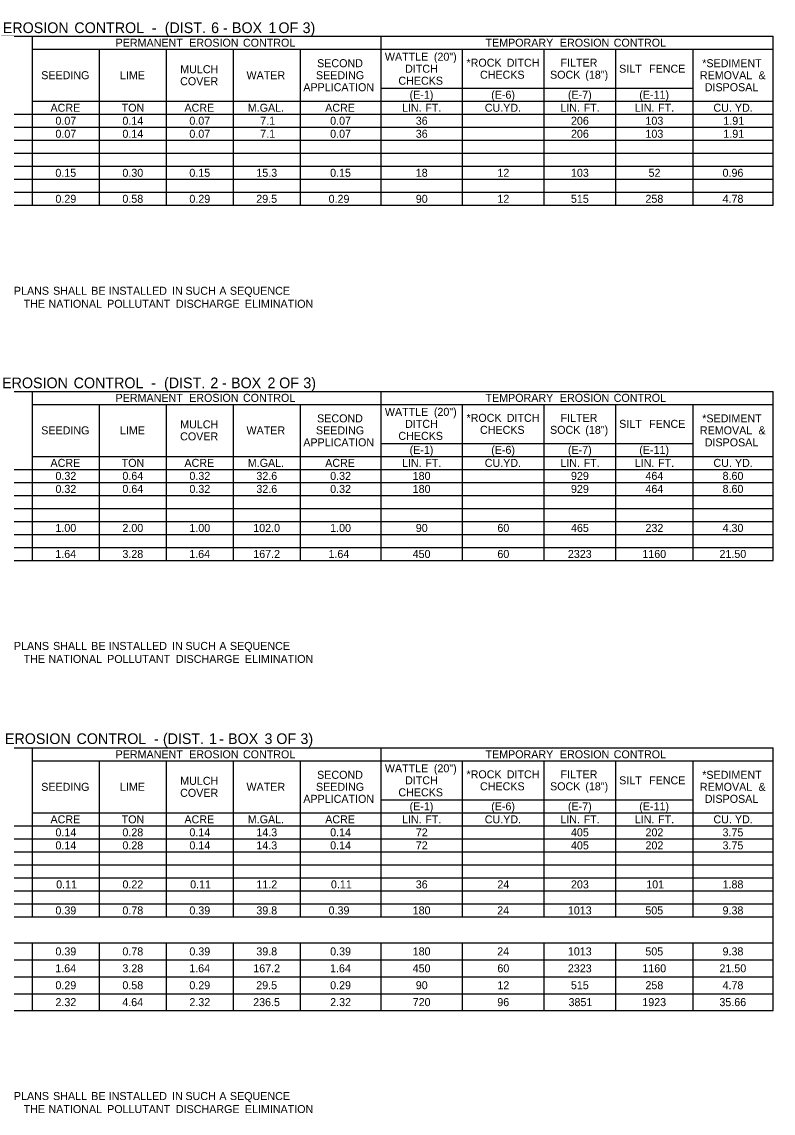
# Model space of a CAD drawing. Extents: x 542596 to 1930787, y -1948294 to 596640.
# Drawn here: x 561680 to 562244, y -1946944 to -1946126 of the extents above; entities that cross this region are included whole.
import ezdxf

# ---------------------------------------------------------------- set-up
doc = ezdxf.new("R2010")
doc.units = 0
doc.layers.add('Default', color=7, linetype='Continuous')

msp = doc.modelspace()

# ---------------------------------------------------------------- linework, layer by layer
at = {"layer": 'Default'}
for p, q in [((561328.63, -1946137.12), (562243.67, -1946137.12)), ((561688.41, -1946263.87), (561688.41, -1946137.12)), ((561949.71, -1946146.87), (561949.71, -1946137.12)), ((561949.71, -1946263.87), (561949.71, -1946137.12)), ((562243.67, -1946195.62), (562243.67, -1946137.12)), ((561688.41, -1946146.87), (562243.67, -1946146.87)), ((561738.62, -1946263.87), (561738.62, -1946146.87)), ((561788.83, -1946263.87), (561788.83, -1946146.87)), ((561839.04, -1946263.87), (561839.04, -1946146.87)), ((561889.26, -1946263.87), (561889.26, -1946146.87)), ((562010.64, -1946263.87), (562010.64, -1946146.87)), ((562072.07, -1946263.87), (562072.07, -1946146.87)), ((562125.69, -1946263.87), (562125.69, -1946146.87)), ((562183.71, -1946263.87), (562183.71, -1946146.87)), ((561949.71, -1946176.12), (562183.71, -1946176.12)), ((561688.41, -1946185.87), (562183.71, -1946185.87)), ((561738.62, -1946263.87), (561738.62, -1946185.87)), ((561788.83, -1946254.12), (561788.83, -1946185.87)), ((561839.04, -1946254.12), (561839.04, -1946185.87)), ((561889.26, -1946254.12), (561889.26, -1946185.87)), ((561949.71, -1946254.12), (561949.71, -1946185.87)), ((562010.64, -1946254.12), (562010.64, -1946185.87)), ((562072.07, -1946254.12), (562072.07, -1946185.87)), ((562125.69, -1946263.87), (562125.69, -1946185.87)), ((562183.71, -1946185.87), (562243.67, -1946185.87)), ((562183.71, -1946263.87), (562183.71, -1946185.87)), ((561328.63, -1946195.62), (562243.67, -1946195.62)), ((562243.67, -1946254.12), (562243.67, -1946195.62)), ((561328.63, -1946205.37), (562243.67, -1946205.37)), ((561328.63, -1946215.12), (562243.67, -1946215.12)), ((561328.63, -1946224.87), (562243.67, -1946224.87)), ((561328.63, -1946234.62), (562243.67, -1946234.62)), ((561328.63, -1946244.37), (562243.67, -1946244.37)), ((561328.63, -1946254.12), (562243.67, -1946254.12)), ((561688.41, -1946263.87), (561688.41, -1946254.12)), ((562183.71, -1946254.12), (562243.67, -1946254.12)), ((562243.67, -1946263.87), (562243.67, -1946254.12)), ((561328.63, -1946263.87), (562243.67, -1946263.87)), ((561328.63, -1946403.3), (562243.67, -1946403.3)), ((561688.41, -1946530.05), (561688.41, -1946403.3)), ((561949.71, -1946413.05), (561949.71, -1946403.3)), ((561949.71, -1946530.05), (561949.71, -1946403.3)), ((562243.67, -1946461.8), (562243.67, -1946403.3)), ((561688.41, -1946413.05), (562243.67, -1946413.05)), ((561738.62, -1946530.05), (561738.62, -1946413.05)), ((561788.83, -1946530.05), (561788.83, -1946413.05)), ((561839.04, -1946530.05), (561839.04, -1946413.05)), ((561889.26, -1946530.05), (561889.26, -1946413.05)), ((562010.64, -1946530.05), (562010.64, -1946413.05)), ((562072.07, -1946530.05), (562072.07, -1946413.05)), ((562125.69, -1946530.05), (562125.69, -1946413.05)), ((562183.71, -1946530.05), (562183.71, -1946413.05)), ((561949.71, -1946442.3), (562183.71, -1946442.3)), ((561688.41, -1946452.05), (562183.71, -1946452.05)), ((561738.62, -1946530.05), (561738.62, -1946452.05)), ((561788.83, -1946520.3), (561788.83, -1946452.05)), ((561839.04, -1946520.3), (561839.04, -1946452.05)), ((561889.26, -1946520.3), (561889.26, -1946452.05)), ((561949.71, -1946520.3), (561949.71, -1946452.05)), ((562010.64, -1946520.3), (562010.64, -1946452.05)), ((562072.07, -1946520.3), (562072.07, -1946452.05)), ((562125.69, -1946530.05), (562125.69, -1946452.05)), ((562183.71, -1946452.05), (562243.67, -1946452.05)), ((562183.71, -1946530.05), (562183.71, -1946452.05)), ((561328.63, -1946461.8), (562243.67, -1946461.8)), ((562243.67, -1946520.3), (562243.67, -1946461.8)), ((561328.63, -1946471.55), (562243.67, -1946471.55)), ((561328.63, -1946481.3), (562243.67, -1946481.3)), ((561328.63, -1946491.05), (562243.67, -1946491.05)), ((561328.63, -1946500.8), (562243.67, -1946500.8)), ((561328.63, -1946510.55), (562243.67, -1946510.55)), ((561328.63, -1946520.3), (562243.67, -1946520.3)), ((561688.41, -1946530.05), (561688.41, -1946520.3)), ((562183.71, -1946520.3), (562243.67, -1946520.3)), ((562243.67, -1946530.05), (562243.67, -1946520.3)), ((561328.63, -1946530.05), (562243.67, -1946530.05)), ((561328.63, -1946670.45), (562243.67, -1946670.45)), ((561688.41, -1946797.2), (561688.41, -1946670.45)), ((561949.71, -1946680.2), (561949.71, -1946670.45)), ((561949.71, -1946797.2), (561949.71, -1946670.45)), ((562243.67, -1946728.95), (562243.67, -1946670.45)), ((561688.41, -1946680.2), (562243.67, -1946680.2)), ((561738.62, -1946797.2), (561738.62, -1946680.2)), ((561788.83, -1946797.2), (561788.83, -1946680.2)), ((561839.04, -1946797.2), (561839.04, -1946680.2)), ((561889.26, -1946797.2), (561889.26, -1946680.2)), ((562010.64, -1946797.2), (562010.64, -1946680.2)), ((562072.07, -1946797.2), (562072.07, -1946680.2)), ((562125.69, -1946797.2), (562125.69, -1946680.2)), ((562183.71, -1946797.2), (562183.71, -1946680.2)), ((561949.71, -1946709.45), (562183.71, -1946709.45)), ((561688.41, -1946719.2), (562183.71, -1946719.2)), ((561738.62, -1946797.2), (561738.62, -1946719.2)), ((561788.83, -1946787.45), (561788.83, -1946719.2)), ((561839.04, -1946787.45), (561839.04, -1946719.2)), ((561889.26, -1946787.45), (561889.26, -1946719.2)), ((561949.71, -1946787.45), (561949.71, -1946719.2)), ((562010.64, -1946787.45), (562010.64, -1946719.2)), ((562072.07, -1946787.45), (562072.07, -1946719.2)), ((562125.69, -1946797.2), (562125.69, -1946719.2)), ((562183.71, -1946719.2), (562243.67, -1946719.2)), ((562183.71, -1946797.2), (562183.71, -1946719.2)), ((561328.63, -1946728.95), (562243.67, -1946728.95)), ((562243.67, -1946787.45), (562243.67, -1946728.95)), ((561328.63, -1946738.7), (562243.67, -1946738.7)), ((561328.63, -1946748.45), (562243.67, -1946748.45)), ((561328.63, -1946758.2), (562243.67, -1946758.2)), ((561328.63, -1946767.95), (562243.67, -1946767.95)), ((561328.63, -1946777.7), (562243.67, -1946777.7)), ((561328.63, -1946787.45), (562243.67, -1946787.45)), ((561688.41, -1946797.2), (561688.41, -1946787.45)), ((562183.71, -1946787.45), (562243.67, -1946787.45)), ((562243.67, -1946797.2), (562243.67, -1946787.45)), ((561328.63, -1946797.2), (562243.67, -1946797.2)), ((562243.67, -1946816.7), (562243.67, -1946797.2)), ((561328.63, -1946816.7), (562243.67, -1946816.7)), ((561328.63, -1946816.7), (562243.67, -1946816.7)), ((561688.41, -1946867.4), (561688.41, -1946816.7)), ((561738.62, -1946867.4), (561738.62, -1946816.7)), ((561788.83, -1946867.4), (561788.83, -1946816.7)), ((561839.04, -1946867.4), (561839.04, -1946816.7)), ((561889.26, -1946867.4), (561889.26, -1946816.7)), ((561949.71, -1946867.4), (561949.71, -1946816.7)), ((562010.64, -1946867.4), (562010.64, -1946816.7)), ((562072.07, -1946867.4), (562072.07, -1946816.7)), ((562125.69, -1946867.4), (562125.69, -1946816.7)), ((562183.71, -1946867.4), (562183.71, -1946816.7)), ((562243.67, -1946854.72), (562243.67, -1946816.7)), ((561328.63, -1946829.37), (562243.67, -1946829.37)), ((561738.62, -1946867.4), (561738.62, -1946829.37)), ((561788.83, -1946867.4), (561788.83, -1946829.37)), ((561839.04, -1946867.4), (561839.04, -1946829.37)), ((561889.26, -1946867.4), (561889.26, -1946829.37)), ((561949.71, -1946867.4), (561949.71, -1946829.37)), ((562010.64, -1946867.4), (562010.64, -1946829.37)), ((562072.07, -1946867.4), (562072.07, -1946829.37)), ((562125.69, -1946867.4), (562125.69, -1946829.37)), ((562183.71, -1946867.4), (562183.71, -1946829.37)), ((561328.63, -1946842.05), (562243.67, -1946842.05)), ((561328.63, -1946854.72), (562243.67, -1946854.72)), ((561688.41, -1946867.4), (561688.41, -1946854.72)), ((562243.67, -1946867.4), (562243.67, -1946854.72)), ((561328.63, -1946867.4), (562243.67, -1946867.4))]:
    msp.add_line(p, q, dxfattribs=at)

# ---------------------------------------------------------------- texts
for s, height, p in [('EROSION', 8, (561666.11, -1946134.79)), (' CONTROL', 8, (561716.77, -1946134.79)), (' -', 8, (561774.81, -1946134.79)), ('  (DIST.', 8, (561781.55, -1946134.79)), (' 6', 8, (561819.28, -1946134.79)), (' -', 8, (561828.2, -1946134.79)), (' BOX', 8, (561834.94, -1946134.79)), (' 1', 8, (561862.26, -1946134.79)), (' OF', 8, (561869.77, -1946134.79)), (' 3)', 8, (561887.88, -1946134.79)), ('PERMANENT', 6, (561750.67, -1946145)), (' EROSION', 6, (561803.6, -1946145)), (' CONTROL', 6, (561843.92, -1946145)), ('TEMPORARY', 6, (562027.97, -1946145)), (' EROSION', 6, (562081.55, -1946145)), (' CONTROL', 6, (562121.88, -1946145)), ('WATTLE', 6, (561952.54, -1946155.5)), (' (20")', 6, (561987.05, -1946155.5)), ('MULCH', 6, (561799.12, -1946164.87)), ('SECOND', 6, (561901.75, -1946160.37)), ('DITCH', 6, (561967.69, -1946164.5)), ('*ROCK', 6, (562013.74, -1946160)), (' DITCH', 6, (562041.67, -1946160)), ('FILTER', 6, (562084.23, -1946160)), ('SILT', 6, (562128.21, -1946164.5)), ('  FENCE', 6, (562146.2, -1946164.5)), ('*SEDIMENT', 6, (562190.48, -1946160.37)), ('SEEDING', 6, (561694.9, -1946169.37)), ('LIME', 6, (561753.92, -1946169.37)), ('WATER', 6, (561848.8, -1946169.37)), ('SEEDING', 6, (561900.87, -1946169.37)), ('CHECKS', 6, (562023.86, -1946169)), ('SOCK', 6, (562076.39, -1946169)), (' (18")', 6, (562100.6, -1946169)), ('REMOVAL', 6, (562188.73, -1946169.37)), (' &', 6, (562230.4, -1946169.37)), ('COVER', 6, (561799.05, -1946173.87)), ('APPLICATION', 6, (561891.4, -1946178.37)), ('CHECKS', 6, (561962.68, -1946173.5)), ('DISPOSAL', 6, (562192.38, -1946178.37)), ('(E-1)', 6, (561971.08, -1946184)), ('(E-6)', 6, (562032.26, -1946184)), ('(E-7)', 6, (562089.79, -1946184)), ('(E-11)', 6, (562143.28, -1946184)), ('ACRE', 6, (561701.84, -1946193.75)), ('TON', 6, (561755.21, -1946193.75)), ('ACRE', 6, (561802.27, -1946193.75)), ('M.GAL.', 6, (561849.77, -1946193.75)), ('ACRE', 6, (561907.81, -1946193.75)), ('LIN.', 6, (561965.38, -1946193.75)), (' FT.', 6, (561980.64, -1946193.75)), ('CU.YD.', 6, (562027.44, -1946193.75)), ('LIN.', 6, (562084.09, -1946193.75)), (' FT.', 6, (562099.35, -1946193.75)), ('LIN.', 6, (562139.91, -1946193.75)), (' FT.', 6, (562155.17, -1946193.75)), ('CU.', 6, (562198.89, -1946193.75)), (' YD.', 6, (562212.75, -1946193.75)), ('0.07', 6, (561705.55, -1946203.5)), ('0.14', 6, (561755.77, -1946203.5)), ('0.07', 6, (561805.97, -1946203.5)), ('7.1', 6, (561859.1, -1946203.5)), ('0.07', 6, (561911.52, -1946203.5)), ('36', 6, (561975.7, -1946203.5)), ('206', 6, (562092.08, -1946203.5)), ('103', 6, (562147.9, -1946203.5)), ('1.91', 6, (562206.3, -1946203.5)), ('0.07', 6, (561705.55, -1946213.25)), ('0.14', 6, (561755.77, -1946213.25)), ('0.07', 6, (561805.97, -1946213.25)), ('7.1', 6, (561859.1, -1946213.25)), ('0.07', 6, (561911.52, -1946213.25)), ('36', 6, (561975.7, -1946213.25)), ('206', 6, (562092.08, -1946213.25)), ('103', 6, (562147.9, -1946213.25)), ('1.91', 6, (562206.3, -1946213.25)), ('0.15', 6, (561705.52, -1946242.5)), ('0.30', 6, (561755.77, -1946242.5)), ('0.15', 6, (561805.95, -1946242.5)), ('15.3', 6, (561856.19, -1946242.5)), ('0.15', 6, (561911.49, -1946242.5)), ('18', 6, (561975.7, -1946242.5)), ('12', 6, (562036.92, -1946242.5)), ('103', 6, (562092.08, -1946242.5)), ('52', 6, (562150.26, -1946242.5)), ('0.96', 6, (562205.72, -1946242.5)), ('0.29', 6, (561705.55, -1946262)), ('0.58', 6, (561755.76, -1946262)), ('0.29', 6, (561805.98, -1946262)), ('29.5', 6, (561856.12, -1946262)), ('0.29', 6, (561910.36, -1946262)), ('90', 6, (561975.72, -1946262)), ('12', 6, (562036.91, -1946262)), ('515', 6, (562092.02, -1946262)), ('258', 6, (562147.9, -1946262)), ('4.78', 6, (562205.72, -1946262)), (' PLANS', 6, (561672.2, -1946330.92)), (' SHALL', 6, (561701.58, -1946330.92)), (' BE', 6, (561730.17, -1946330.92)), (' INSTALLED', 6, (561743.24, -1946330.92)), (' IN', 6, (561790.77, -1946330.92)), (' SUCH', 6, (561800.8, -1946330.92)), (' A', 6, (561826.21, -1946330.92)), (' SEQUENCE', 6, (561834.14, -1946330.92)), (' THE', 6, (561679.49, -1946340.67)), (' NATIONAL', 6, (561698.14, -1946340.67)), (' POLLUTANT', 6, (561742.1, -1946340.67)), (' DISCHARGE', 6, (561793.64, -1946340.67)), (' ELIMINATION', 6, (561845.36, -1946340.67)), ('EROSION', 8, (561665.57, -1946400.96)), (' CONTROL', 8, (561716.23, -1946400.96)), ('  (DIST.', 8, (561781.01, -1946400.96)), (' 2', 8, (561818.74, -1946400.96)), (' BOX', 8, (561834.24, -1946400.96)), (' 2', 8, (561861.55, -1946400.96)), (' OF', 8, (561870.31, -1946400.96)), (' 3)', 8, (561888.42, -1946400.96)), (' -', 8, (561774.27, -1946400.96)), (' -', 8, (561827.49, -1946400.96)), ('PERMANENT', 6, (561750.67, -1946411.17)), (' EROSION', 6, (561803.6, -1946411.17)), (' CONTROL', 6, (561843.92, -1946411.17)), ('TEMPORARY', 6, (562027.97, -1946411.17)), (' EROSION', 6, (562081.55, -1946411.17)), (' CONTROL', 6, (562121.88, -1946411.17)), ('SECOND', 6, (561901.75, -1946426.55)), ('WATTLE', 6, (561952.54, -1946421.67)), (' (20")', 6, (561987.05, -1946421.67)), ('*ROCK', 6, (562013.74, -1946426.17)), (' DITCH', 6, (562041.67, -1946426.17)), ('FILTER', 6, (562084.23, -1946426.17)), ('*SEDIMENT', 6, (562190.48, -1946426.55)), ('MULCH', 6, (561799.12, -1946431.05)), ('DITCH', 6, (561967.69, -1946430.67)), (' (18")', 6, (562100.6, -1946435.17)), ('SILT', 6, (562128.21, -1946430.67)), ('  FENCE', 6, (562146.2, -1946430.67)), ('SEEDING', 6, (561694.9, -1946435.55)), ('LIME', 6, (561753.92, -1946435.55)), ('COVER', 6, (561799.05, -1946440.05)), ('WATER', 6, (561848.8, -1946435.55)), ('SEEDING', 6, (561900.87, -1946435.55)), ('CHECKS', 6, (561962.68, -1946439.67)), ('CHECKS', 6, (562023.86, -1946435.17)), ('SOCK', 6, (562076.39, -1946435.17)), ('REMOVAL', 6, (562188.73, -1946435.55)), (' &', 6, (562230.4, -1946435.55)), ('APPLICATION', 6, (561891.4, -1946444.55)), ('(E-1)', 6, (561971.08, -1946450.17)), ('(E-6)', 6, (562032.26, -1946450.17)), ('(E-7)', 6, (562089.79, -1946450.17)), ('(E-11)', 6, (562143.28, -1946450.17)), ('DISPOSAL', 6, (562192.38, -1946444.55)), ('ACRE', 6, (561701.84, -1946459.92)), ('TON', 6, (561755.21, -1946459.92)), ('ACRE', 6, (561802.27, -1946459.92)), ('M.GAL.', 6, (561849.77, -1946459.92)), ('ACRE', 6, (561907.81, -1946459.92)), ('LIN.', 6, (561965.38, -1946459.92)), (' FT.', 6, (561980.64, -1946459.92)), ('CU.YD.', 6, (562027.44, -1946459.92)), ('LIN.', 6, (562084.09, -1946459.92)), (' FT.', 6, (562099.35, -1946459.92)), ('LIN.', 6, (562139.91, -1946459.92)), (' FT.', 6, (562155.17, -1946459.92)), ('CU.', 6, (562198.89, -1946459.92)), (' YD.', 6, (562212.75, -1946459.92)), ('0.32', 6, (561705.58, -1946469.67)), ('0.64', 6, (561755.77, -1946469.67)), ('0.32', 6, (561806, -1946469.67)), ('32.6', 6, (561856.19, -1946469.67)), ('0.32', 6, (561911.55, -1946469.67)), ('180', 6, (561973.39, -1946469.67)), ('929', 6, (562092.08, -1946469.67)), ('464', 6, (562147.91, -1946469.67)), ('8.60', 6, (562205.73, -1946469.67)), ('0.32', 6, (561705.58, -1946479.42)), ('0.64', 6, (561755.77, -1946479.42)), ('0.32', 6, (561806, -1946479.42)), ('32.6', 6, (561856.19, -1946479.42)), ('0.32', 6, (561911.55, -1946479.42)), ('180', 6, (561973.39, -1946479.42)), ('929', 6, (562092.08, -1946479.42)), ('464', 6, (562147.91, -1946479.42)), ('8.60', 6, (562205.73, -1946479.42)), ('1.00', 6, (561705.56, -1946508.67)), ('2.00', 6, (561755.77, -1946508.67)), ('1.00', 6, (561805.98, -1946508.67)), ('102.0', 6, (561853.87, -1946508.67)), ('1.00', 6, (561911.53, -1946508.67)), ('90', 6, (561975.72, -1946508.67)), ('60', 6, (562036.9, -1946508.67)), ('465', 6, (562092.06, -1946508.67)), ('232', 6, (562147.93, -1946508.67)), ('4.30', 6, (562205.73, -1946508.67)), ('1.64', 6, (561705.45, -1946528.17)), ('3.28', 6, (561755.76, -1946528.17)), ('1.64', 6, (561805.88, -1946528.17)), ('167.2', 6, (561853.88, -1946528.17)), ('1.64', 6, (561910.26, -1946528.17)), ('450', 6, (561973.39, -1946528.17)), ('60', 6, (562036.9, -1946528.17)), ('2323', 6, (562089.74, -1946528.17)), ('1160', 6, (562145.59, -1946528.17)), ('21.50', 6, (562203.41, -1946528.17)), (' PLANS', 6, (561672.2, -1946597.1)), (' SHALL', 6, (561701.58, -1946597.1)), (' BE', 6, (561730.17, -1946597.1)), (' INSTALLED', 6, (561743.24, -1946597.1)), (' IN', 6, (561790.77, -1946597.1)), (' SUCH', 6, (561800.8, -1946597.1)), (' A', 6, (561826.21, -1946597.1)), (' SEQUENCE', 6, (561834.14, -1946597.1)), (' THE', 6, (561679.49, -1946606.85)), (' NATIONAL', 6, (561698.14, -1946606.85)), (' POLLUTANT', 6, (561742.1, -1946606.85)), (' DISCHARGE', 6, (561793.64, -1946606.85)), (' ELIMINATION', 6, (561845.36, -1946606.85)), ('EROSION', 8, (561667.71, -1946667.62)), (' CONTROL', 8, (561718.37, -1946667.62)), (' -', 8, (561776.4, -1946667.62)), (' (DIST.', 8, (561783.15, -1946667.62)), (' 1', 8, (561817.77, -1946667.62)), (' -', 8, (561825.28, -1946667.62)), (' BOX', 8, (561832.02, -1946667.62)), (' 3', 8, (561859.34, -1946667.62)), (' OF', 8, (561868.17, -1946667.62)), (' 3)', 8, (561886.28, -1946667.62)), ('PERMANENT', 6, (561750.67, -1946678.32)), (' EROSION', 6, (561803.6, -1946678.32)), (' CONTROL', 6, (561843.92, -1946678.32)), ('TEMPORARY', 6, (562027.97, -1946678.32)), (' EROSION', 6, (562081.55, -1946678.32)), (' CONTROL', 6, (562121.88, -1946678.32)), ('SECOND', 6, (561901.75, -1946693.7)), ('WATTLE', 6, (561952.54, -1946688.82)), (' (20")', 6, (561987.05, -1946688.82)), ('*ROCK', 6, (562013.74, -1946693.32)), (' DITCH', 6, (562041.67, -1946693.32)), ('FILTER', 6, (562084.23, -1946693.32)), ('*SEDIMENT', 6, (562190.48, -1946693.7)), ('SEEDING', 6, (561694.9, -1946702.7)), ('LIME', 6, (561753.92, -1946702.7)), ('MULCH', 6, (561799.12, -1946698.2)), ('WATER', 6, (561848.8, -1946702.7)), ('SEEDING', 6, (561900.87, -1946702.7)), ('DITCH', 6, (561967.69, -1946697.82)), ('CHECKS', 6, (562023.86, -1946702.32)), ('SOCK', 6, (562076.39, -1946702.32)), (' (18")', 6, (562100.6, -1946702.32)), ('SILT', 6, (562128.21, -1946697.82)), ('  FENCE', 6, (562146.2, -1946697.82)), ('REMOVAL', 6, (562188.73, -1946702.7)), (' &', 6, (562230.4, -1946702.7)), ('COVER', 6, (561799.05, -1946707.2)), ('APPLICATION', 6, (561891.4, -1946711.7)), ('CHECKS', 6, (561962.68, -1946706.82)), ('DISPOSAL', 6, (562192.38, -1946711.7)), ('(E-1)', 6, (561971.08, -1946717.32)), ('(E-6)', 6, (562032.26, -1946717.32)), ('(E-7)', 6, (562089.79, -1946717.32)), ('(E-11)', 6, (562143.28, -1946717.32)), ('ACRE', 6, (561701.84, -1946727.07)), ('TON', 6, (561755.21, -1946727.07)), ('ACRE', 6, (561802.27, -1946727.07)), ('M.GAL.', 6, (561849.77, -1946727.07)), ('ACRE', 6, (561907.81, -1946727.07)), ('LIN.', 6, (561965.38, -1946727.07)), (' FT.', 6, (561980.64, -1946727.07)), ('CU.YD.', 6, (562027.44, -1946727.07)), ('LIN.', 6, (562084.09, -1946727.07)), (' FT.', 6, (562099.35, -1946727.07)), ('LIN.', 6, (562139.91, -1946727.07)), (' FT.', 6, (562155.17, -1946727.07)), ('CU.', 6, (562198.89, -1946727.07)), (' YD.', 6, (562212.75, -1946727.07)), ('0.14', 6, (561705.56, -1946736.82)), ('0.28', 6, (561755.76, -1946736.82)), ('0.14', 6, (561805.99, -1946736.82)), ('14.3', 6, (561856.19, -1946736.82)), ('0.14', 6, (561911.53, -1946736.82)), ('72', 6, (561975.74, -1946736.82)), ('405', 6, (562092.06, -1946736.82)), ('202', 6, (562147.93, -1946736.82)), ('3.75', 6, (562205.7, -1946736.82)), ('0.14', 6, (561705.56, -1946746.57)), ('0.28', 6, (561755.76, -1946746.57)), ('0.14', 6, (561805.99, -1946746.57)), ('14.3', 6, (561856.19, -1946746.57)), ('0.14', 6, (561911.53, -1946746.57)), ('72', 6, (561975.74, -1946746.57)), ('405', 6, (562092.06, -1946746.57)), ('202', 6, (562147.93, -1946746.57)), ('3.75', 6, (562205.7, -1946746.57)), ('0.11', 6, (561706.13, -1946775.82)), ('0.22', 6, (561755.79, -1946775.82)), ('0.11', 6, (561806.55, -1946775.82)), ('11.2', 6, (561856.22, -1946775.82)), ('0.11', 6, (561912.1, -1946775.82)), ('36', 6, (561975.7, -1946775.82)), ('24', 6, (562036.9, -1946775.82)), ('203', 6, (562092.08, -1946775.82)), ('101', 6, (562148.48, -1946775.82)), ('1.88', 6, (562205.72, -1946775.82)), ('0.39', 6, (561705.55, -1946795.32)), ('0.78', 6, (561755.76, -1946795.32)), ('0.39', 6, (561805.98, -1946795.32)), ('39.8', 6, (561856.18, -1946795.32)), ('0.39', 6, (561910.36, -1946795.32)), ('180', 6, (561973.39, -1946795.32)), ('24', 6, (562036.79, -1946795.32)), ('1013', 6, (562089.74, -1946795.32)), ('505', 6, (562147.84, -1946795.32)), ('9.38', 6, (562205.72, -1946795.32)), ('0.39', 6, (561705.55, -1946826.04)), ('0.78', 6, (561755.76, -1946826.04)), ('0.39', 6, (561805.98, -1946826.04)), ('39.8', 6, (561856.18, -1946826.04)), ('0.39', 6, (561911.52, -1946826.04)), ('180', 6, (561973.39, -1946826.04)), ('24', 6, (562036.79, -1946826.04)), ('1013', 6, (562089.74, -1946826.04)), ('505', 6, (562147.84, -1946826.04)), ('9.38', 6, (562205.72, -1946826.04)), ('1.64', 6, (561705.45, -1946838.71)), ('3.28', 6, (561755.76, -1946838.71)), ('1.64', 6, (561805.88, -1946838.71)), ('167.2', 6, (561853.88, -1946838.71)), ('1.64', 6, (561911.42, -1946838.71)), ('450', 6, (561973.39, -1946838.71)), ('60', 6, (562036.9, -1946838.71)), ('2323', 6, (562089.74, -1946838.71)), ('1160', 6, (562145.59, -1946838.71)), ('21.50', 6, (562203.41, -1946838.71)), ('0.29', 6, (561705.55, -1946851.39)), ('0.58', 6, (561755.76, -1946851.39)), ('0.29', 6, (561805.98, -1946851.39)), ('29.5', 6, (561856.12, -1946851.39)), ('0.29', 6, (561911.52, -1946851.39)), ('90', 6, (561975.72, -1946851.39)), ('12', 6, (562036.91, -1946851.39)), ('515', 6, (562092.02, -1946851.39)), ('258', 6, (562147.9, -1946851.39)), ('4.78', 6, (562205.72, -1946851.39)), ('2.32', 6, (561705.57, -1946864.06)), ('4.64', 6, (561755.67, -1946864.06)), ('2.32', 6, (561805.99, -1946864.06)), ('236.5', 6, (561853.79, -1946864.06)), ('2.32', 6, (561911.54, -1946864.06)), ('720', 6, (561973.39, -1946864.06)), ('96', 6, (562036.84, -1946864.06)), ('3851', 6, (562090.24, -1946864.06)), ('1923', 6, (562145.56, -1946864.06)), ('35.66', 6, (562203.35, -1946864.06)), (' PLANS', 6, (561672.2, -1946934.45)), (' SHALL', 6, (561701.58, -1946934.45)), (' BE', 6, (561730.17, -1946934.45)), (' INSTALLED', 6, (561743.24, -1946934.45)), (' IN', 6, (561790.77, -1946934.45)), (' SUCH', 6, (561800.8, -1946934.45)), (' A', 6, (561826.21, -1946934.45)), (' SEQUENCE', 6, (561834.14, -1946934.45)), (' THE', 6, (561679.49, -1946944.2)), (' NATIONAL', 6, (561698.14, -1946944.2)), (' POLLUTANT', 6, (561742.1, -1946944.2)), (' DISCHARGE', 6, (561793.64, -1946944.2)), (' ELIMINATION', 6, (561845.36, -1946944.2))]:
    msp.add_text(s, height=height, dxfattribs=at).set_placement(p)

doc.saveas('drawing.dxf')
